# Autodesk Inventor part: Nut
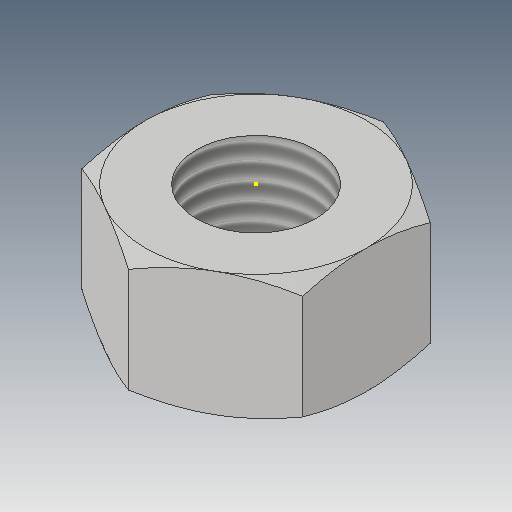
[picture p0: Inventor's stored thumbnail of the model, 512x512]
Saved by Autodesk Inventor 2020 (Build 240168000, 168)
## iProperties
Created: 2016-05
Part Number: Nut
Material: Generic
Document SubType Name: Modeling
Designer: CADCIM
Density: 1 g/cm^3
Appearance: Default
Author: CADCIM
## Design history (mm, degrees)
sketch "Sketch1"
  geometry: L1 (9.6, -5.543)-(0, -11.085); L2 (0, -11.085)-(-9.6, -5.543); L3 (-9.6, -5.543)-(-9.6, 5.543); L4 (-9.6, 5.543)-(0, 11.085); L5 (0, 11.085)-(9.6, 5.543); L6 (9.6, 5.543)-(9.6, -5.543); 2 further points
  constraints: 12 end point, 1 coincident, 1 vertical alignment, 13 other
  dimensions: "d0" = 19.2 distance between parallel lines of L3 L6
extrude "Extrusion1" new body sketch "Sketch1" distance "d1" = 10.8; taper "d2" = 0 deg
sketch "Sketch2"
  geometry: L1 (0, 11.085)-(-9.6, 5.543) reference; C1 r 9.6 at (0, 0); 1 further point
  constraints: 1 centre point, 1 coincident, 1 tangent
extrude "Extrusion2" sketch "Sketch2" distance "d3" = 10.8; taper "d4" = 60 deg
workplane "Work Plane1"
sketch "Sketch3"
  geometry: L1 (0, -11.085)-(9.6, -5.543) reference; C1 r 9.6 at (0, 0); 1 further point
  constraints: 1 centre point, 1 coincident, 1 tangent
extrude "Extrusion3" sketch "Sketch3" distance "d5" = 10.8; taper "d6" = 60 deg
sketch "Sketch4"
  geometry: 1 further point
hole "Hole1" diameter "d9" = 10.376; stored, may be unused: countersink angle "d13" = 90 deg, drill point angle "d15" = 118 deg; dims "d7" = 10, "d8" = 10, "d10" = 24, "d11" = 4, "d12" = 2, "d14" = 31.3
body "Solid1"
